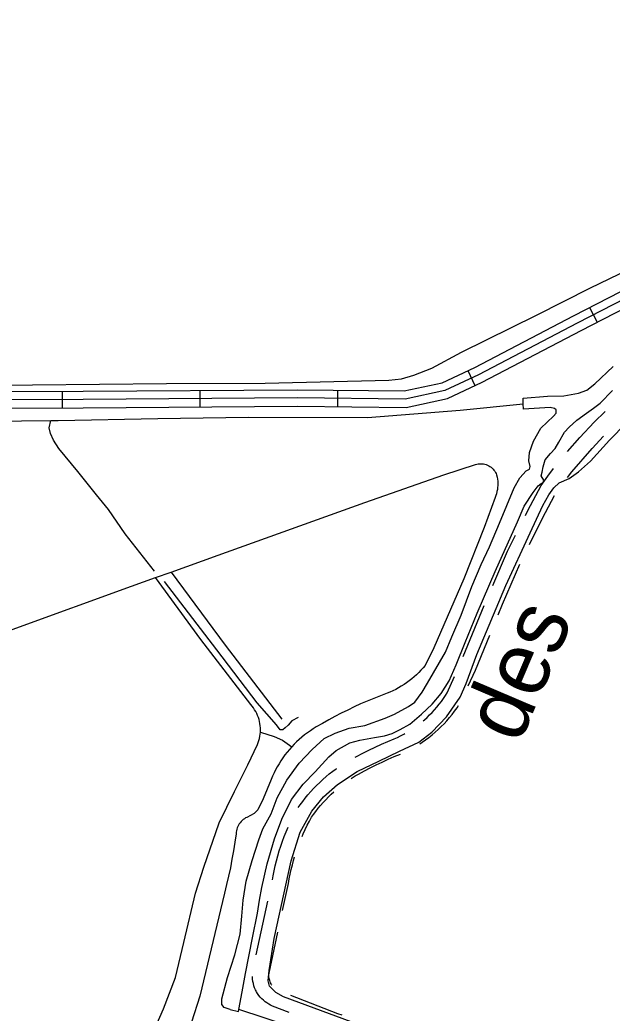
# Model space of a CAD drawing. Extents: x 3419139 to 3457078, y 540382 to 565875.
# Drawn here: x 3447297 to 3448373, y 558183 to 559989 of the extents above; entities that cross this region are included whole.
import ezdxf

# ---------------------------------------------------------------- set-up
doc = ezdxf.new("R2010")
doc.units = 0
for name, color, linetype in [('V-DTCH-CNTR', 7, 'Continuous'), ('V-RIVR-IDEN', 7, 'Continuous'), ('V-ROAD-CNTR', 7, 'Continuous'), ('V-TOPO-SHOR', 7, 'Continuous')]:
    doc.layers.add(name, color=color, linetype=linetype)

msp = doc.modelspace()

# ---------------------------------------------------------------- linework, layer by layer
at = {"layer": 'V-DTCH-CNTR'}
for points in [[(3447571.3, 558984.7), (3447656.9, 559015.5), (3447923.5, 559111.4), (3448066.9, 559161.3), (3448124.4, 559180.2), (3448126.8, 559180.9), (3448129.3, 559181.4), (3448131.8, 559181.6), (3448134.3, 559181.7), (3448136.8, 559181.6), (3448139.2, 559181.2), (3448141.7, 559180.7), (3448144.1, 559180), (3448146.4, 559179.1), (3448148.6, 559178), (3448150.8, 559176.7), (3448152.8, 559175.2), (3448154.7, 559173.6), (3448156.5, 559171.9), (3448158.1, 559170), (3448159.6, 559167.9), (3448160.9, 559165.8), (3448162, 559163.6), (3448163, 559161.3), (3448163.8, 559157.5), (3448164.4, 559153.8), (3448164.9, 559150), (3448165, 559146.2), (3448165, 559142.3), (3448164.8, 559138.5), (3448164.3, 559134.7), (3448163.6, 559131), (3448162.7, 559127.2), (3448161.6, 559123.6), (3448160.2, 559120), (3448140.6, 559065.9), (3448103.3, 558972.6), (3448049.1, 558846.8), (3448032.9, 558815), (3448029.2, 558810.6), (3448025.4, 558806.2), (3448021.5, 558802), (3448017.4, 558797.9), (3448013.1, 558794), (3448008.7, 558790.2), (3448004.2, 558786.6), (3447999.5, 558783.2), (3447994.7, 558780), (3447989.8, 558776.9), (3447984.8, 558774), (3447979.7, 558771.3), (3447974.5, 558768.8), (3447969.2, 558766.5), (3447963.8, 558764.4), (3447951.7, 558759.8), (3447939.6, 558755), (3447927.7, 558750), (3447915.8, 558744.8), (3447904, 558739.4), (3447892.3, 558733.8), (3447880.7, 558728), (3447869.2, 558722)], [(3446582.1, 558624.8), (3446798.4, 558703.6), (3447056.1, 558797.5), (3447289.6, 558882.5), (3447499.3, 558958.8), (3447543.2, 558974.6), (3447571.3, 558984.7)], [(3447571.3, 558984.7), (3447670, 558851.4), (3447772.7, 558717.4)], [(3447514.9, 558093), (3447557.6, 558190.4), (3447579.3, 558247.2), (3447594.9, 558310.8), (3447615.9, 558400.7), (3447630.8, 558448.1), (3447658.6, 558528.5), (3447686.4, 558585.3), (3447710.8, 558634), (3447728.4, 558671.2), (3447729.8, 558674.8), (3447731, 558678.5), (3447732, 558682.2), (3447732.8, 558686), (3447733.3, 558689.9), (3447733.7, 558693.7), (3447733.8, 558697.6), (3447733.7, 558701.5), (3447733.4, 558705.3), (3447732.9, 558709.2), (3447732.1, 558713), (3447731.2, 558716.7), (3447730, 558720.4), (3447728.6, 558724), (3447727, 558727.6), (3447725.2, 558731), (3447723.3, 558734.3), (3447721.1, 558737.5), (3447718.8, 558740.6), (3447716.3, 558743.6), (3447625.7, 558862), (3447543.2, 558974.6)], [(3447869.2, 558722), (3447857.8, 558715.8), (3447846.5, 558709.5), (3447835.3, 558702.9), (3447829.8, 558699.6), (3447824.5, 558696.1), (3447819.2, 558692.4), (3447814.1, 558688.5), (3447809.1, 558684.5), (3447804.3, 558680.3), (3447799.6, 558676), (3447795, 558671.5), (3447790.6, 558666.9), (3447786.4, 558662.1), (3447782.3, 558657.2), (3447778.4, 558652.1), (3447774.6, 558646.9), (3447771, 558641.6), (3447767.6, 558636.2), (3447764.4, 558630.7), (3447761.3, 558625), (3447758.5, 558619.3), (3447755.8, 558613.5), (3447753.4, 558607.6), (3447738.5, 558572.4), (3447729, 558552.1), (3447722.2, 558545.4), (3447709.3, 558538.6), (3447706.9, 558537.5), (3447704.6, 558536.1), (3447702.4, 558534.5)], [(3447733.7, 558693.7), (3447758.7, 558685.6), (3447773.6, 558678.8), (3447790.6, 558666.9)], [(3447702.4, 558534.5), (3447700.4, 558532.8), (3447698.5, 558530.9), (3447696.7, 558528.9), (3447695.1, 558526.7), (3447693.7, 558524.4), (3447692.5, 558522), (3447691.6, 558519.5), (3447690.8, 558516.9), (3447690.2, 558514.2), (3447689.8, 558511.6), (3447689.7, 558508.9), (3447687.4, 558493.3), (3447684.9, 558477.8), (3447682.1, 558462.4), (3447679.1, 558446.9), (3447675.9, 558431.6), (3447672.3, 558416.3), (3447668.6, 558401), (3447664.6, 558385.8), (3447623.9, 558213.4), (3447608.3, 558166)]]:
    msp.add_lwpolyline(points, dxfattribs=at)
at = {"layer": 'V-ROAD-CNTR'}
for p, q in [((3448332, 559465.8), (3448345.7, 559439.1)), ((3448110.6, 559350.9), (3448123.3, 559323.8)), ((3447373.7, 559313.3), (3447373.8, 559283.3)), ((3447623.6, 559314.9), (3447623.9, 559284.9)), ((3447873.9, 559315.4), (3447873.6, 559285.4)), ((3448102.2, 558831.3), (3448140.4, 558923.7)), ((3447726, 558288.4), (3447747.2, 558386.1))]:
    msp.add_line(p, q, dxfattribs=at)
for points in [[(3449325.2, 560903), (3449337.7, 560851.7), (3449329, 560663.6), (3449324.8, 560567.1), (3449305.8, 560482.1), (3449295.7, 560448.5), (3449277.8, 560336.6), (3449268.6, 560206.1), (3449257.1, 560060.4), (3449244.7, 559982.3), (3449216.7, 559935.3), (3449162.4, 559879.3), (3449061.2, 559821.8), (3448983, 559773.6), (3448944.1, 559747.5), (3448883.7, 559724.5), (3448839.9, 559710.3), (3448309.6, 559437.4), (3448129.9, 559343.5), (3448068.6, 559314.6), (3447996.7, 559298.9), (3447801.3, 559301.2), (3447411.9, 559298.3), (3447018, 559297.9)], [(3447017.8, 559312.9), (3447411.8, 559313.3), (3447801.4, 559316.2), (3447995.2, 559313.9), (3448063.8, 559328.9), (3448123.2, 559356.9), (3448302.7, 559450.7), (3448834.1, 559724.2), (3448878.7, 559738.7), (3448937.1, 559760.9), (3448974.9, 559786.2), (3449053.6, 559834.7), (3449153.1, 559891.3), (3449204.8, 559944.5), (3449230.3, 559987.5), (3449242.2, 560062.2), (3449253.6, 560207.2), (3449262.9, 560338.3), (3449281.1, 560451.9), (3449291.3, 560485.9), (3449309.9, 560569.1), (3449314, 560664.3), (3449322.6, 560850.2), (3449314.8, 560882.4)], [(3447018.2, 559282.9), (3447411.9, 559283.3), (3447801.3, 559286.2), (3447998.3, 559283.9), (3448073.5, 559300.3), (3448136.6, 559330), (3448316.5, 559424), (3448845.7, 559696.4), (3448888.6, 559710.3), (3448951, 559734.1), (3448991.1, 559761), (3449068.9, 559808.9), (3449171.7, 559867.3), (3449228.7, 559926.1), (3449259.1, 559977.1), (3449272, 560058.7), (3449283.6, 560204.9), (3449292.7, 560334.9), (3449310.4, 560445.2), (3449320.3, 560478.3), (3449339.7, 560565.2), (3449344, 560662.9), (3449352.8, 560853.1), (3449343.8, 560890.1)], [(3448291.8, 559203.8), (3448314.1, 559229.3), (3448340.2, 559257.4), (3448360.1, 559276.9)], [(3448291.6, 559156.3), (3448299.7, 559167.2), (3448336.4, 559209.2), (3448357.3, 559231.7)], [(3448215.3, 559087.3), (3448219.8, 559096.3), (3448244.1, 559141.9), (3448256.2, 559159.1), (3448266.5, 559172.9)], [(3448222.6, 559034.9), (3448246.5, 559082.5), (3448268.4, 559123.8)], [(3448156, 558960.5), (3448183, 559022.7), (3448197.4, 559051.5)], [(3448165.9, 558906.9), (3448173.8, 558926), (3448205.3, 558998.8)], [(3448111.5, 558777.9), (3448124.3, 558806.2), (3448150.6, 558870)], [(3448029.2, 558713.9), (3448031.7, 558715.9), (3448036.5, 558720.3), (3448041.2, 558724.8), (3448045.8, 558729.5), (3448050.2, 558734.3), (3448054.4, 558739.2), (3448058.5, 558744.3), (3448062.5, 558749.5), (3448066.2, 558754.8), (3448069.8, 558760.2), (3448072.9, 558765.2), (3448086.2, 558794.7)], [(3448023.4, 558672.3), (3448027.8, 558675.1), (3448033.9, 558679.4), (3448039.9, 558683.8), (3448045.7, 558688.5), (3448051.4, 558693.3), (3448057, 558698.3), (3448062.3, 558703.5), (3448067.5, 558708.8), (3448072.6, 558714.3), (3448077.5, 558720), (3448082.2, 558725.8), (3448086.7, 558731.8), (3448091, 558737.8), (3448093.8, 558742.2)], [(3447906.2, 558648.2), (3447908.5, 558649.5), (3447919.7, 558655.4), (3447931, 558661), (3447942.3, 558666.4), (3447953.8, 558671.6), (3447965.3, 558676.6), (3447976.7, 558681.3), (3447982.6, 558684), (3447988.5, 558686.8), (3447994.3, 558689.9), (3447996.4, 558691.1)], [(3447898.6, 558609.2), (3447900.2, 558610.2), (3447906.1, 558613.8), (3447912.1, 558617.3), (3447922.7, 558623.1), (3447933.3, 558628.6), (3447944.1, 558634), (3447955, 558639.2), (3447966, 558644.2), (3447977, 558649), (3447988, 558653.6)], [(3447802.5, 558556.3), (3447806, 558561.3), (3447810.6, 558567.6), (3447815.3, 558573.7), (3447820.2, 558579.7), (3447825.3, 558585.5), (3447830.5, 558591.2), (3447835.9, 558596.8), (3447841.5, 558602.2), (3447847.1, 558607.5), (3447853, 558612.6), (3447858.9, 558617.5), (3447865.1, 558622.3), (3447871.3, 558626.9), (3447872, 558627.4)], [(3447809.6, 558504), (3447811.6, 558508.6), (3447815.2, 558516.4), (3447819, 558524.1), (3447823, 558531.7), (3447826.8, 558538.7), (3447830.5, 558543.9), (3447834.5, 558549.5), (3447838.8, 558555), (3447843.2, 558560.4), (3447847.7, 558565.6), (3447852.4, 558570.7), (3447857.2, 558575.6), (3447862.1, 558580.5), (3447866.9, 558584.9)], [(3447755.6, 558425.2), (3447756.8, 558432.3), (3447758.5, 558441.4), (3447760.5, 558450.5), (3447762.8, 558459.5), (3447765.2, 558468.5), (3447767.8, 558477.4), (3447770.7, 558486.2), (3447773.8, 558495), (3447777.1, 558503.7), (3447780.5, 558512.3), (3447784.2, 558520.7)], [(3447774.1, 558368.9), (3447784.7, 558418), (3447786.3, 558426.9), (3447787.9, 558435.3), (3447789.8, 558443.7), (3447791.8, 558452), (3447794.1, 558460.3), (3447795.9, 558466.5)], [(3447753.2, 558235.6), (3447752, 558237.8), (3447751.2, 558239.7), (3447750.6, 558241.6), (3447750, 558243.5), (3447749.6, 558245.5), (3447749.3, 558247.4), (3447749.2, 558249.4), (3447749.2, 558251.4), (3447749.3, 558253.4), (3447749.5, 558255.3), (3447765.7, 558329.8)], [(3447726.5, 558222), (3447724.9, 558225.1), (3447723.3, 558228.7), (3447721.9, 558232.5), (3447720.9, 558236.4), (3447720, 558240.3), (3447719.5, 558244.3), (3447719.2, 558248.3), (3447719.2, 558249.1)], [(3447785.9, 558183.6), (3447755.9, 558195.3), (3447752.3, 558196.9), (3447748.8, 558198.9), (3447745.4, 558201), (3447742.2, 558203.4), (3447739.1, 558205.9), (3447736.2, 558208.7), (3447733.5, 558211.7), (3447731, 558214.8), (3447728.7, 558218.1), (3447726.9, 558221.1)], [(3447754.5, 558233.6), (3447754, 558234.3), (3447752.7, 558236.5)], [(3447882.1, 558178.6), (3447874.4, 558181.2), (3447788.8, 558214.6)]]:
    msp.add_lwpolyline(points, dxfattribs=at)
at = {"layer": 'V-TOPO-SHOR'}
for points in [[(3447055.2, 559324.4), (3447319.6, 559324.9), (3447563.1, 559327.4), (3447742.4, 559328), (3447966.9, 559333.9), (3447989.9, 559335.9), (3448012.3, 559342.6), (3448045.4, 559355.5), (3448098.9, 559384.5), (3448235.6, 559452.1), (3448333.7, 559501.4), (3448454.1, 559559.5), (3448605, 559637.1), (3448752.5, 559708.7), (3448902.7, 559785), (3449030.6, 559848.5), (3449078.6, 559873.5), (3449107.1, 559889.7), (3449133.4, 559909.3), (3449152.4, 559926.9), (3449169.3, 559946.5), (3449178.8, 559960.7), (3449195.1, 559993.2)], [(3447678.7, 558189), (3447667.8, 558193), (3447663.8, 558198.4), (3447663.8, 558208.6), (3447674, 558247.1), (3447687.5, 558288.4), (3447697, 558326.3), (3447699.8, 558358.7), (3447702.5, 558387.8), (3447707.9, 558422.3), (3447718.8, 558460.2), (3447731, 558497.4), (3447738.4, 558517.6), (3447753.3, 558544.7), (3447764.2, 558573.8), (3447781.8, 558606.2), (3447804.1, 558637.3), (3447827.8, 558661.7), (3447849.5, 558681.9), (3447869.8, 558691.4), (3447894.8, 558700.8), (3447923.2, 558705.6), (3447960.4, 558719.1), (3447977.3, 558726.5), (3448003, 558740), (3448014.5, 558748.1), (3448027.4, 558766.4), (3448037.6, 558782.6), (3448070.1, 558838.7), (3448081.6, 558867.1), (3448098.5, 558906.3), (3448118.2, 558958.4), (3448135.1, 558998.3), (3448150, 559030.7), (3448168.3, 559073.3), (3448194.7, 559137.6), (3448204.9, 559155.8), (3448216.4, 559168.7), (3448222.5, 559172), (3448223.9, 559176.8), (3448221.2, 559186.9), (3448222.5, 559201.8), (3448230, 559222.8), (3448243.5, 559246.4), (3448266.5, 559268.1), (3448271.3, 559273.5), (3448271.3, 559279.6), (3448267.9, 559282.3), (3448260.5, 559283.6), (3448211.8, 559281), (3448211.4, 559290.6), (3448211.1, 559300.6), (3448255.1, 559304.6), (3448284.8, 559305.3), (3448311.9, 559310), (3448326.8, 559315.4), (3448341.7, 559326.9), (3448374.8, 559358.6)], [(3448229.2, 559129.4), (3448238.7, 559141.6), (3448244.1, 559145.7), (3448247.5, 559147.7), (3448248.9, 559151.7), (3448244.1, 559159.9), (3448245.5, 559166.6), (3448247.5, 559176.1), (3448250.9, 559188.9), (3448261.1, 559200.4), (3448269.2, 559209.2), (3448276, 559220.7), (3448286.1, 559239), (3448294.9, 559248.4), (3448308.5, 559260.6), (3448326.1, 559273.4), (3448338.9, 559282.9), (3448351.1, 559291.7), (3448373.4, 559314.7)], [(3447193.1, 559258.5), (3447352.7, 559260.2), (3447366.3, 559260.4), (3447547.5, 559263.6), (3447711.9, 559266.2), (3447928.4, 559266), (3448096.8, 559278.8), (3448211.4, 559290.6)], [(3448333.8, 559186.5), (3448368.3, 559224.3), (3448398.1, 559255.4), (3448413.7, 559275), (3448422.5, 559282.4), (3448434.6, 559289.9)], [(3447367.6, 559209.6), (3447357.5, 559224.5), (3447352.1, 559236.7), (3447350, 559246.8), (3447352.7, 559260.2)], [(3447541.3, 558986.3), (3447487.9, 559054), (3447457.5, 559098.6), (3447435.8, 559125), (3447402.1, 559167.7), (3447367.6, 559209.6)], [(3447954.3, 558146.4), (3447775.7, 558212.2), (3447761.6, 558220.3), (3447750.1, 558231.8), (3447748, 558241.3), (3447749.4, 558260.2), (3447758.9, 558318.4), (3447789.5, 558459.7), (3447805.7, 558511.8), (3447827.4, 558549.7), (3447848.4, 558576), (3447874.1, 558598.3), (3447909.3, 558622), (3447949.2, 558640.9), (3447986.4, 558659.1), (3448021.6, 558675.3), (3448045.3, 558693.6), (3448071.7, 558721.3), (3448096.7, 558757.1), (3448107.6, 558782.1), (3448127.2, 558834.9), (3448179.4, 558960), (3448224.1, 559056), (3448247.2, 559105.4), (3448258, 559125), (3448266.8, 559137.8), (3448276.9, 559146.6), (3448294.5, 559154.7), (3448311.5, 559166.9), (3448333.8, 559186.5)], [(3447700.3, 558221.4), (3447706.4, 558254.6), (3447719.3, 558319.5), (3447728.2, 558364.1), (3447732.2, 558387.8), (3447736.3, 558410.8), (3447745.8, 558454.1), (3447759.4, 558499.4), (3447772.9, 558535.2), (3447790.5, 558571), (3447811.5, 558598.8), (3447833.2, 558621.1), (3447858.2, 558648.8), (3447871.1, 558660.3), (3447896.1, 558673.8), (3447914.4, 558679.2), (3447940.8, 558683.9), (3447959, 558686.6), (3447973.2, 558691.3), (3447987.5, 558698.1), (3448005.1, 558708.2), (3448026.7, 558726.4), (3448045.7, 558744.7), (3448061.9, 558763.6), (3448076.8, 558786.6), (3448089.7, 558815.7), (3448105.9, 558856.3), (3448127.6, 558909.7), (3448160.1, 558985.4), (3448200.8, 559076), (3448213, 559104.4), (3448229.2, 559129.4)], [(3447802.2, 558720.3), (3447790.7, 558714.2), (3447783.9, 558706.1), (3447778.5, 558701.4), (3447774.4, 558698), (3447769.7, 558698), (3447762.9, 558706.8), (3447727.8, 558746.7), (3447654.8, 558843.5), (3447559.5, 558967.3)], [(3447678.7, 558189), (3447694.2, 558185.6), (3447694.8, 558188.9), (3447700.3, 558221.4)], [(3448588.2, 557911), (3448420.5, 557965.2), (3448379.9, 557976.8), (3448325.8, 557993), (3448241.3, 558016.8), (3448105.4, 558054.7), (3447917.4, 558115.7), (3447694.8, 558188.9)]]:
    msp.add_lwpolyline(points, dxfattribs=at)

# ---------------------------------------------------------------- texts
at = {"layer": 'V-RIVR-IDEN'}
msp.add_text('des', height=116, rotation=66.8858, dxfattribs=at).set_placement((3448204, 558669.7))

doc.saveas('drawing.dxf')
